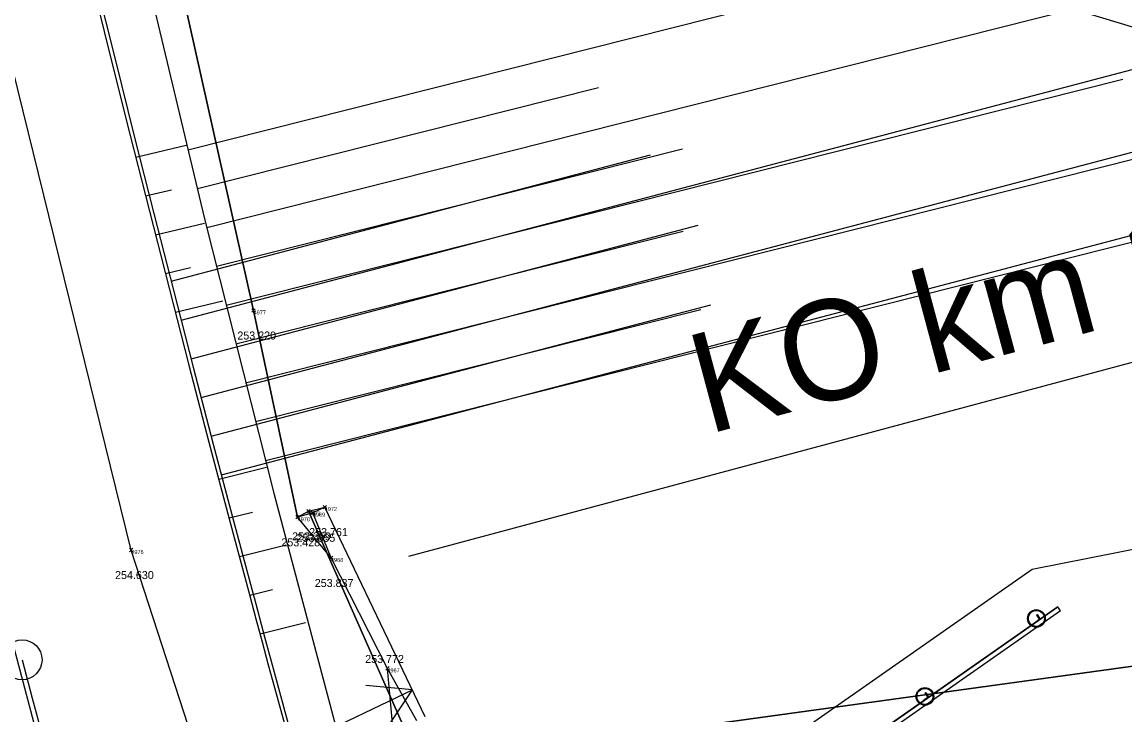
# Model space of a CAD drawing. Extents: x -809973 to -809318, y -1011363 to -1010505.
# Drawn here: x -809841.74 to -809827.96, y -1010978.8 to -1010970.15 of the extents above; entities that cross this region are included whole.
import ezdxf

# ---------------------------------------------------------------- set-up
doc = ezdxf.new("R2010")
doc.units = 0
for name, color, linetype in [('18b - zaměření - čísla bodů', 7, 'Continuous'), ('18c - zaměření - výšky', 7, 'Continuous'), ('Návrh', 7, 'Continuous'), ('SO03 - Železniční svršek', 7, 'Continuous'), ('SO04 - Železniční spodek', 7, 'Continuous'), ('SO_01', 7, 'Continuous'), ('stav_stav', 7, 'Continuous')]:
    doc.layers.add(name, color=color, linetype=linetype)

# ---------------------------------------------------------------- blocks, each defined once
blk = doc.blocks.new('POINT_DISPLAY')
for p, q in [((-0.021, -0.021), (0.021, 0.021)), ((-0.021, 0.021), (0.021, -0.021))]:
    blk.add_line(p, q)

msp = doc.modelspace()

# ---------------------------------------------------------------- linework, layer by layer
at = {"layer": 'Návrh'}
msp.add_circle((-809841.74, -1010978.113), 0.25, dxfattribs=at)
msp.add_arc((-809483.868, -1010882.207), 370.5, 195.00213, 204.78693, dxfattribs=at)
at = {"layer": 'SO03 - Železniční svršek'}
msp.add_line((-809836.91, -1010976.819), (-809823.253, -1010973.159), dxfattribs=at)
at = {"layer": 'SO04 - Železniční spodek'}
for p, q in [((-809830.46, -1010969.425), (-809839.668, -1010971.746)), ((-809828.601, -1010969.988), (-809839.431, -1010972.718)), ((-809827.99, -1010970.865), (-809839.191, -1010973.688)), ((-809834.54, -1010970.969), (-809839.55, -1010972.232)), ((-809833.491, -1010971.736), (-809839.311, -1010973.203)), ((-809827.796, -1010971.848), (-809838.947, -1010974.658)), ((-809833.481, -1010972.765), (-809839.069, -1010974.173)), ((-809827.602, -1010972.83), (-809838.699, -1010975.627)), ((-809833.261, -1010973.741), (-809838.823, -1010975.143))]:
    msp.add_line(p, q, dxfattribs=at)
for points in [[(-809844.502, -1010948.259), (-809843.86, -1010951.753), (-809843.202, -1010955.243), (-809842.522, -1010958.729), (-809841.813, -1010962.21), (-809841.069, -1010965.683), (-809840.285, -1010969.148), (-809839.459, -1010972.604), (-809838.59, -1010976.05), (-809837.678, -1010979.484), (-809836.721, -1010982.905), (-809835.72, -1010986.314), (-809834.673, -1010989.708), (-809833.585, -1010993.088), (-809832.46, -1010996.457), (-809831.306, -1010999.816), (-809830.127, -1011003.167), (-809828.93, -1011006.512), (-809827.721, -1011009.854), (-809826.507, -1011013.193)], [(-809840.871, -1010969.622), (-809840.633, -1010970.585), (-809840.392, -1010971.548), (-809840.149, -1010972.51), (-809839.903, -1010973.472), (-809839.655, -1010974.433), (-809839.405, -1010975.393), (-809839.152, -1010976.352), (-809838.896, -1010977.314)], [(-809839.689, -1010971.689), (-809840.319, -1010971.839)], [(-809839.872, -1010972.247), (-809840.196, -1010972.324)], [(-809839.46, -1010972.663), (-809840.073, -1010972.808)], [(-809839.634, -1010973.218), (-809839.949, -1010973.293)], [(-809839.231, -1010973.636), (-809839.825, -1010973.777)], [(-809838.685, -1010975.711), (-809839.282, -1010975.862)], [(-809838.862, -1010976.272), (-809839.154, -1010976.346)], [(-809838.442, -1010976.682), (-809839.025, -1010976.829)], [(-809838.61, -1010977.24), (-809838.896, -1010977.312)], [(-809838.199, -1010977.652), (-809838.766, -1010977.795)]]:
    msp.add_lwpolyline(points, dxfattribs=at)
for centre, radius, start, end in [((-809453.305, -1010872.818), 406.4, 193.63597, 201.43276), ((-809483.922, -1010882.181), 367.5, 195.00277, 200.92799)]:
    msp.add_arc(centre, radius, start, end, dxfattribs=at)
at = {"layer": 'SO_01'}
for p, q in [((-809839.753, -1010973.87), (-809826.947, -1010970.496)), ((-809839.502, -1010974.838), (-809826.884, -1010971.514)), ((-809839.878, -1010973.385), (-809833.888, -1010971.808)), ((-809839.249, -1010975.805), (-809826.82, -1010972.531)), ((-809839.628, -1010974.354), (-809833.295, -1010972.686)), ((-809839.376, -1010975.322), (-809833.136, -1010973.678)), ((-809828.802, -1010977.453), (-809834.866, -1010981.695)), ((-809828.8, -1010977.457), (-809834.863, -1010981.699)), ((-809828.768, -1010977.502), (-809834.832, -1010981.744)), ((-809828.768, -1010977.502), (-809828.802, -1010977.453))]:
    msp.add_line(p, q, dxfattribs=at)
for points in [[(-809841.69, -1010966.027), (-809826.948, -1010970.488)], [(-809841.69, -1010966.027), (-809841.518, -1010966.753), (-809841.286, -1010967.719), (-809841.053, -1010968.684), (-809840.817, -1010969.648), (-809840.578, -1010970.611), (-809840.338, -1010971.574), (-809840.095, -1010972.537), (-809839.849, -1010973.498), (-809839.601, -1010974.459), (-809839.351, -1010975.419), (-809839.098, -1010976.378), (-809838.841, -1010977.34)], [(-809835.659, -1010981.554), (-809829.119, -1010976.981), (-809826.574, -1010976.477), (-809826.434, -1010978.736)], [(-809829.02, -1010977.605), (-809829.077, -1010977.645), (-809829.078, -1010977.643)], [(-809829.077, -1010977.637), (-809829.037, -1010977.609)], [(-809829.034, -1010977.596), (-809829.063, -1010977.556)], [(-809829.062, -1010977.549), (-809829.06, -1010977.548), (-809829.02, -1010977.605)], [(-809830.413, -1010978.58), (-809830.47, -1010978.62), (-809830.471, -1010978.618)], [(-809830.47, -1010978.611), (-809830.43, -1010978.583)], [(-809830.427, -1010978.571), (-809830.456, -1010978.53)], [(-809830.455, -1010978.524), (-809830.453, -1010978.522), (-809830.413, -1010978.58)]]:
    msp.add_lwpolyline(points, dxfattribs=at)
for centre, radius in [((-809829.068, -1010977.597), 0.11), ((-809829.068, -1010977.597), 0.1), ((-809830.461, -1010978.571), 0.11), ((-809830.461, -1010978.571), 0.1)]:
    msp.add_circle(centre, radius, dxfattribs=at)
for centre, radius, start, end in [((-809483.868, -1010882.207), 367.5, 195.00213, 200.05975), ((-809829.075, -1010977.641), 0.0045, 124.9748, 214.9749), ((-809829.059, -1010977.553), 0.0045, 124.9748, 214.9749), ((-809829.042, -1010977.601), 0.009, 304.9748, 34.9749), ((-809830.468, -1010978.615), 0.0045, 124.9748, 214.9749), ((-809830.452, -1010978.527), 0.0045, 124.9748, 214.9749), ((-809830.435, -1010978.576), 0.009, 304.9748, 34.9749)]:
    msp.add_arc(centre, radius, start, end, dxfattribs=at)
at = {"layer": 'stav_stav'}
for p, q in [((-809838.847, -1010973.75), (-809841.894, -1010960.179)), ((-809841.894, -1010960.179), (-809838.847, -1010973.75)), ((-809840.375, -1010976.742), (-809844.107, -1010961.611)), ((-809838.297, -1010976.333), (-809838.847, -1010973.75)), ((-809838.847, -1010973.75), (-809838.297, -1010976.333)), ((-809841.189, -1010980.417), (-809842.723, -1010974.633)), ((-809838.297, -1010976.333), (-809838.163, -1010976.258)), ((-809838.297, -1010976.333), (-809838.163, -1010976.258)), ((-809838.163, -1010976.258), (-809837.958, -1010976.205)), ((-809836.936, -1010979.029), (-809838.163, -1010976.258)), ((-809838.163, -1010976.258), (-809836.936, -1010979.029)), ((-809837.958, -1010976.205), (-809838.107, -1010976.276)), ((-809836.702, -1010978.825), (-809837.958, -1010976.205)), ((-809838.107, -1010976.276), (-809838.297, -1010976.333)), ((-809837.88, -1010976.841), (-809838.297, -1010976.333)), ((-809837.88, -1010976.841), (-809838.297, -1010976.333)), ((-809837.88, -1010976.841), (-809838.107, -1010976.276)), ((-809839.533, -1010979.34), (-809840.375, -1010976.742)), ((-809837.176, -1010978.22), (-809837.88, -1010976.841)), ((-809837.176, -1010978.22), (-809837.88, -1010976.841)), ((-809825.985, -1010977.935), (-809837.013, -1010979.451)), ((-809837.013, -1010979.451), (-809825.985, -1010977.935)), ((-809837.103, -1010978.997), (-809837.176, -1010978.22)), ((-809836.807, -1010978.875), (-809837.176, -1010978.22)), ((-809837.103, -1010978.997), (-809837.176, -1010978.22)), ((-809838.667, -1010979.352), (-809836.864, -1010978.487))]:
    msp.add_line(p, q, dxfattribs=at)
msp.add_lwpolyline([(-809837.185, -1010978.974), (-809836.864, -1010978.487), (-809837.444, -1010978.433)], dxfattribs=at)

# ---------------------------------------------------------------- block references
at = {"layer": '18b - zaměření - čísla bodů'}
for p in [(-809838.847, -1010973.75), (-809838.163, -1010976.258), (-809838.107, -1010976.276), (-809837.958, -1010976.205), (-809838.297, -1010976.333), (-809840.375, -1010976.742), (-809837.88, -1010976.841), (-809837.176, -1010978.22)]:
    msp.add_blockref('POINT_DISPLAY', p, dxfattribs=at)

# ---------------------------------------------------------------- texts
for s, p in [('4977', (-809838.847, -1010973.8)), ('4971', (-809838.163, -1010976.308)), ('4972', (-809837.958, -1010976.255)), ('4970', (-809838.297, -1010976.383)), ('4969', (-809838.107, -1010976.326)), ('4976', (-809840.375, -1010976.792)), ('4968', (-809837.88, -1010976.891)), ('4967', (-809837.176, -1010978.27))]:
    msp.add_text(s, height=0.05, dxfattribs=at).set_placement(p)
at = {"layer": '18c - zaměření - výšky'}
for s, p in [('253.220', (-809839.05, -1010974.113)), ('253.359', (-809838.366, -1010976.621)), ('253.855', (-809838.31, -1010976.639)), ('253.761', (-809838.153, -1010976.568)), ('253.428', (-809838.5, -1010976.696)), ('254.630', (-809840.578, -1010977.105)), ('253.837', (-809838.083, -1010977.204)), ('253.772', (-809837.453, -1010978.153))]:
    msp.add_text(s, height=0.1, dxfattribs=at).set_placement(p)
at = {"layer": 'SO03 - Železniční svršek'}
msp.add_text('KO km 190,163 259', height=1.25, rotation=15.0021, dxfattribs=at).set_placement((-809833.176, -1010975.3))

doc.saveas('drawing.dxf')
